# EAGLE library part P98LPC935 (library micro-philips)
8-bit microcontroller with accelerated two-clock core 4 KB/ 8 KB/ 8 KB 3 V byte-erasable Flash with 8-bit A/D converter Source: http://www.nxp.com .. UM_P89LPC933_934_935_1.pdf
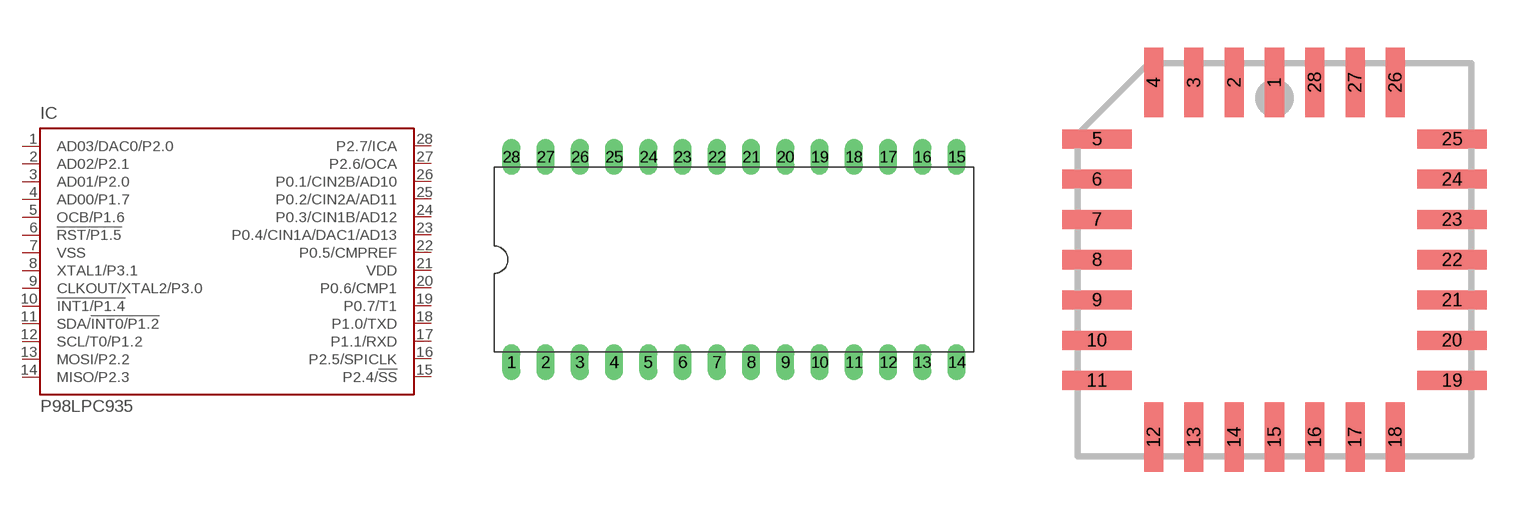
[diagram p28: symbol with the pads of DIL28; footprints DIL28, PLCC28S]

Designator prefix IC

## P98LPC935P (OC_FARNELL: unknown; OC_NEWARK: unknown)  [DIL28]
1  AD03/DAC0/P2.0
2  AD02/P2.1
3  AD01/P2.0
4  AD00/P1.7
5  OCB/P1.6
6  !RST/P1.5
7  VSS
8  XTAL1/P3.1
9  CLKOUT/XTAL2/P3.0
10  !INT1/P1.4
11  SDA/!INT0/P1.2
12  SCL/T0/P1.2
13  MOSI/P2.2
14  MISO/P2.3
15  P2.4/!SS
16  P2.5/SPICLK
17  P1.1/RXD
18  P1.0/TXD
19  P0.7/T1
20  P0.6/CMP1
21  VDD
22  P0.5/CMPREF
23  P0.4/CIN1A/DAC1/AD13
24  P0.3/CIN1B/AD12
25  P0.2/CIN2A/AD11
26  P0.1/CIN2B/AD10
27  P2.6/OCA
28  P2.7/ICA

## P98LPC935L (OC_FARNELL: unknown; OC_NEWARK: unknown)  [PLCC28S]
Pads as for DIL28

## P98LPC935H (OC_FARNELL: unknown; OC_NEWARK: unknown)  [HVQFN28]
1  OCB/P1.6
2  !RST/P1.5
3  VSS
4  XTAL1/P3.1
5  CLKOUT/XTAL2/P3.0
6  !INT1/P1.4
7  SDA/!INT0/P1.2
8  SCL/T0/P1.2
9  MOSI/P2.2
10  MISO/P2.3
11  P2.4/!SS
12  P2.5/SPICLK
13  P1.1/RXD
14  P1.0/TXD
15  P0.7/T1
16  P0.6/CMP1
17  VDD
18  P0.5/CMPREF
19  P0.4/CIN1A/DAC1/AD13
20  P0.3/CIN1B/AD12
21  P0.2/CIN2A/AD11
22  P0.1/CIN2B/AD10
23  P2.6/OCA
24  P2.7/ICA
25  AD03/DAC0/P2.0
26  AD02/P2.1
27  AD01/P2.0
28  AD00/P1.7

## Footprint DIL28 (pad centres in mm)
Dual In Line
drill 0.813 pad 1.27 long: 1 -16.51,-7.62; 2 -13.97,-7.62; 3 -11.43,-7.62; 4 -8.89,-7.62; 5 -6.35,-7.62; 6 -3.81,-7.62; 7 -1.27,-7.62; 8 1.27,-7.62; 9 3.81,-7.62; 10 6.35,-7.62; 11 8.89,-7.62; 12 11.43,-7.62; 13 13.97,-7.62; 14 16.51,-7.62; 15 16.51,7.62; 16 13.97,7.62; 17 11.43,7.62; 18 8.89,7.62; 19 6.35,7.62; 20 3.81,7.62; 21 1.27,7.62; 22 -1.27,7.62; 23 -3.81,7.62; 24 -6.35,7.62; 25 -8.89,7.62; 26 -11.43,7.62; 27 -13.97,7.62; 28 -16.51,7.62

## Footprint PLCC28S (pad centres in mm)
PLASTIC LEADED CHIP CARRIER square
smd 0.6 x 2.2: 1 0,5.6; 2 -1.27,5.6; 3 -2.54,5.6; 4 -3.81,5.6; 12 -3.81,-5.6; 13 -2.54,-5.6; 14 -1.27,-5.6; 15 0,-5.6; 16 1.27,-5.6; 17 2.54,-5.6; 18 3.81,-5.6; 26 3.81,5.6; 27 2.54,5.6; 28 1.27,5.6
smd 2.2 x 0.6: 5 -5.6,3.81; 6 -5.6,2.54; 7 -5.6,1.27; 8 -5.6,0; 9 -5.6,-1.27; 10 -5.6,-2.54; 11 -5.6,-3.81; 19 5.6,-3.81; 20 5.6,-2.54; 21 5.6,-1.27; 22 5.6,0; 23 5.6,1.27; 24 5.6,2.54; 25 5.6,3.81

## Footprint HVQFN28 (pad centres in mm)
plastic thermal enhanced very thin quad flat package SOT993-1 no leads; 24 terminals; body 4 x 4 x 0.85 mm Source: SOT993-1.pdf
smd 0.5 x 0.3: 1 -2.3,1.5; 2 -2.3,1; 3 -2.3,0.5; 4 -2.3,0; 5 -2.3,-0.5; 6 -2.3,-1; 7 -2.3,-1.5; 15 2.3,-1.5; 16 2.3,-1; 17 2.3,-0.5; 18 2.3,0; 19 2.3,0.5; 20 2.3,1; 21 2.3,1.5
smd 0.3 x 0.5: 8 -1.5,-2.3; 9 -1,-2.3; 10 -0.5,-2.3; 11 0,-2.3; 12 0.5,-2.3; 13 1,-2.3; 14 1.5,-2.3; 22 1.5,2.3; 23 1,2.3; 24 0.5,2.3; 25 0,2.3; 26 -0.5,2.3; 27 -1,2.3; 28 -1.5,2.3
smd 2.25 x 2.25: TH 0,0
